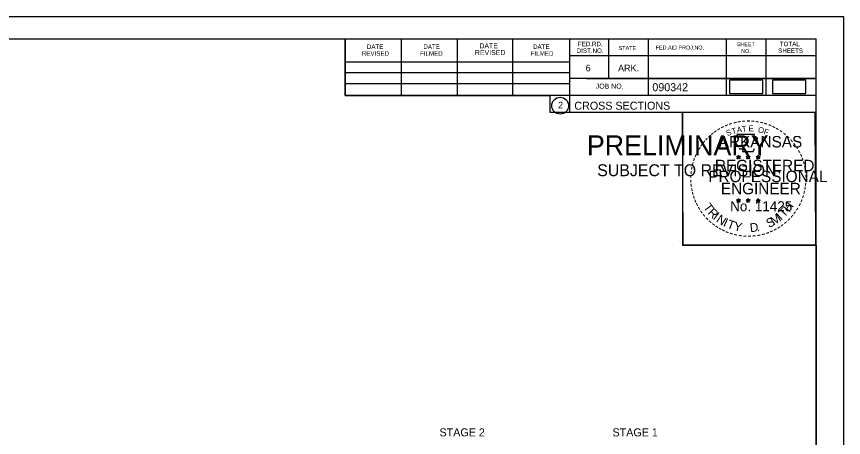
# Model space of a CAD drawing. Extents: x 1370515 to 1370849, y 383299 to 386073.
# Drawn here: x 1370704.3 to 1370848.7, y 385572.7 to 385646.1 of the extents above; entities that cross this region are included whole.
import ezdxf

# ---------------------------------------------------------------- set-up
doc = ezdxf.new("R2010")
doc.units = 0
for name, color, linetype in [('R_Axis Annot', 7, 'Continuous'), ('R_Border', 7, 'Continuous'), ('R_Border PE', 7, 'Continuous'), ('R_Border Prem', 7, 'Continuous'), ('R_Detour', 7, 'Continuous'), ('R_No Plot', 7, 'Continuous')]:
    doc.layers.add(name, color=color, linetype=linetype)

msp = doc.modelspace()

# ---------------------------------------------------------------- linework, layer by layer
at = {"layer": 'R_Border'}
for p, q in [((1370527.8, 385642.25), (1370843.98, 385642.25)), ((1370761.72, 385632.37), (1370761.72, 385642.25)), ((1370800.88, 385642.25), (1370800.88, 385629.45)), ((1370807.72, 385642.25), (1370807.72, 385635.31)), ((1370814.66, 385642.25), (1370814.66, 385632.37)), ((1370828.24, 385642.25), (1370828.24, 385632.37)), ((1370835.18, 385642.25), (1370835.18, 385632.37)), ((1370843.98, 385436.79), (1370843.98, 385642.25)), ((1370771.58, 385632.37), (1370771.58, 385642.05)), ((1370781.34, 385632.37), (1370781.34, 385642.05)), ((1370791.02, 385632.37), (1370791.02, 385642.05)), ((1370843.98, 385639.31), (1370800.88, 385639.31)), ((1370843.98, 385639.33), (1370843.98, 385639.33)), ((1370761.72, 385638.23), (1370800.88, 385638.23)), ((1370761.72, 385636.37), (1370800.88, 385636.37)), ((1370843.98, 385635.31), (1370800.88, 385635.31)), ((1370803.84, 385635.31), (1370843.98, 385635.31)), ((1370761.72, 385632.37), (1370761.72, 385634.43)), ((1370761.72, 385634.43), (1370800.88, 385634.43)), ((1370843.98, 385632.37), (1370761.72, 385632.37)), ((1370800.88, 385629.45), (1370843.98, 385629.45))]:
    msp.add_line(p, q, dxfattribs=at)
msp.add_circle((1370799.27, 385630.58), 1.47, dxfattribs=at)
at = {"layer": 'R_Border PE'}
for p, q in [((1370830.42, 385621.96), (1370830.37, 385621.71)), ((1370830.42, 385621.59), (1370830.42, 385621.96)), ((1370830.42, 385621.96), (1370830.46, 385621.71)), ((1370832.09, 385621.96), (1370832.04, 385621.71)), ((1370832.09, 385621.59), (1370832.09, 385621.96)), ((1370832.09, 385621.96), (1370832.13, 385621.71)), ((1370833.85, 385621.95), (1370833.81, 385621.69)), ((1370833.85, 385621.58), (1370833.85, 385621.95)), ((1370833.85, 385621.95), (1370833.9, 385621.7)), ((1370830.07, 385621.7), (1370830.42, 385621.59)), ((1370830.07, 385621.7), (1370830.32, 385621.66)), ((1370830.07, 385621.7), (1370830.3, 385621.58)), ((1370830.2, 385621.3), (1370830.42, 385621.59)), ((1370830.2, 385621.3), (1370830.33, 385621.54)), ((1370830.2, 385621.3), (1370830.41, 385621.51)), ((1370830.63, 385621.3), (1370830.41, 385621.51)), ((1370830.76, 385621.7), (1370830.42, 385621.59)), ((1370830.63, 385621.3), (1370830.42, 385621.59)), ((1370830.76, 385621.7), (1370830.48, 385621.65)), ((1370830.63, 385621.3), (1370830.49, 385621.59)), ((1370830.76, 385621.7), (1370830.56, 385621.6)), ((1370831.74, 385621.7), (1370832.09, 385621.59)), ((1370831.74, 385621.7), (1370831.99, 385621.66)), ((1370831.74, 385621.7), (1370831.97, 385621.58)), ((1370831.87, 385621.3), (1370832.09, 385621.59)), ((1370831.87, 385621.3), (1370832, 385621.54)), ((1370831.87, 385621.3), (1370832.08, 385621.51)), ((1370832.3, 385621.3), (1370832.08, 385621.51)), ((1370832.43, 385621.7), (1370832.09, 385621.59)), ((1370832.3, 385621.3), (1370832.09, 385621.59)), ((1370832.43, 385621.7), (1370832.15, 385621.65)), ((1370832.3, 385621.3), (1370832.16, 385621.59)), ((1370832.43, 385621.7), (1370832.23, 385621.6)), ((1370833.5, 385621.69), (1370833.85, 385621.58)), ((1370833.5, 385621.69), (1370833.75, 385621.65)), ((1370833.5, 385621.69), (1370833.74, 385621.57)), ((1370833.63, 385621.28), (1370833.85, 385621.58)), ((1370833.63, 385621.28), (1370833.76, 385621.53)), ((1370833.63, 385621.28), (1370833.85, 385621.5)), ((1370834.2, 385621.69), (1370833.85, 385621.58)), ((1370834.06, 385621.28), (1370833.85, 385621.58)), ((1370834.06, 385621.28), (1370833.85, 385621.5)), ((1370834.2, 385621.69), (1370833.91, 385621.64)), ((1370834.06, 385621.28), (1370833.93, 385621.57)), ((1370834.2, 385621.69), (1370833.99, 385621.59)), ((1370830.06, 385614.13), (1370830.41, 385614.02)), ((1370830.06, 385614.13), (1370830.32, 385614.09)), ((1370830.06, 385614.13), (1370830.3, 385614.01)), ((1370830.2, 385613.72), (1370830.41, 385614.02)), ((1370830.2, 385613.72), (1370830.32, 385613.97)), ((1370830.2, 385613.72), (1370830.41, 385613.94)), ((1370830.41, 385614.38), (1370830.37, 385614.13)), ((1370830.41, 385614.02), (1370830.41, 385614.38)), ((1370830.41, 385614.38), (1370830.46, 385614.13)), ((1370830.76, 385614.13), (1370830.41, 385614.02)), ((1370830.62, 385613.72), (1370830.41, 385614.02)), ((1370830.62, 385613.72), (1370830.41, 385613.94)), ((1370830.76, 385614.13), (1370830.47, 385614.08)), ((1370830.62, 385613.72), (1370830.49, 385614.01)), ((1370830.76, 385614.13), (1370830.55, 385614.03)), ((1370831.73, 385614.13), (1370832.08, 385614.02)), ((1370831.73, 385614.13), (1370831.98, 385614.09)), ((1370831.73, 385614.13), (1370831.97, 385614.01)), ((1370831.86, 385613.72), (1370832.08, 385614.02)), ((1370831.86, 385613.72), (1370831.99, 385613.97)), ((1370831.86, 385613.72), (1370832.08, 385613.94)), ((1370832.08, 385614.38), (1370832.04, 385614.13)), ((1370832.08, 385614.02), (1370832.08, 385614.38)), ((1370832.08, 385614.38), (1370832.13, 385614.13)), ((1370832.43, 385614.13), (1370832.08, 385614.02)), ((1370832.29, 385613.72), (1370832.08, 385614.02)), ((1370832.29, 385613.72), (1370832.08, 385613.94)), ((1370832.43, 385614.13), (1370832.14, 385614.08)), ((1370832.29, 385613.72), (1370832.16, 385614.01)), ((1370832.43, 385614.13), (1370832.22, 385614.03)), ((1370833.5, 385614.12), (1370833.85, 385614.01)), ((1370833.5, 385614.12), (1370833.75, 385614.08)), ((1370833.5, 385614.12), (1370833.74, 385614)), ((1370833.63, 385613.71), (1370833.85, 385614.01)), ((1370833.63, 385613.71), (1370833.76, 385613.96)), ((1370833.63, 385613.71), (1370833.85, 385613.93)), ((1370833.85, 385614.37), (1370833.81, 385614.12)), ((1370833.85, 385614.01), (1370833.85, 385614.37)), ((1370833.85, 385614.37), (1370833.9, 385614.12)), ((1370834.19, 385614.12), (1370833.85, 385614.01)), ((1370834.06, 385613.71), (1370833.85, 385614.01)), ((1370834.06, 385613.71), (1370833.85, 385613.93)), ((1370834.19, 385614.12), (1370833.91, 385614.07)), ((1370834.06, 385613.71), (1370833.92, 385614)), ((1370834.19, 385614.12), (1370833.99, 385614.02))]:
    msp.add_line(p, q, dxfattribs=at)
for points in [[(1370830.11, 385625.58), (1370830.38, 385624.75)], [(1370833.62, 385624.66), (1370833.76, 385624.94), (1370833.08, 385624.92), (1370833.22, 385625.58), (1370830.11, 385625.58)], [(1370830.42, 385621.96), (1370830.63, 385621.3), (1370830.07, 385621.7), (1370830.76, 385621.7), (1370830.2, 385621.3), (1370830.42, 385621.96)], [(1370830.6, 385623.16), (1370830.6, 385623.07), (1370831.16, 385623.05), (1370831.11, 385622.58), (1370832.98, 385622.58), (1370833.18, 385623.12)], [(1370832.09, 385621.96), (1370832.3, 385621.3), (1370831.74, 385621.7), (1370832.43, 385621.7), (1370831.87, 385621.3), (1370832.09, 385621.96)], [(1370833.85, 385621.95), (1370834.06, 385621.28), (1370833.5, 385621.69), (1370834.2, 385621.69), (1370833.63, 385621.28), (1370833.85, 385621.95)], [(1370830.41, 385614.38), (1370830.62, 385613.72), (1370830.06, 385614.13), (1370830.76, 385614.13), (1370830.2, 385613.72), (1370830.41, 385614.38)], [(1370832.08, 385614.38), (1370832.29, 385613.72), (1370831.73, 385614.13), (1370832.43, 385614.13), (1370831.86, 385613.72), (1370832.08, 385614.38)], [(1370833.85, 385614.37), (1370834.06, 385613.71), (1370833.5, 385614.12), (1370834.19, 385614.12), (1370833.63, 385613.71), (1370833.85, 385614.37)]]:
    msp.add_lwpolyline(points, dxfattribs=at)
for centre, radius in [((1370830.41, 385621.59), 0.172), ((1370830.41, 385621.59), 0.145), ((1370830.41, 385621.59), 0.116), ((1370830.41, 385621.59), 0.0991), ((1370830.41, 385621.59), 0.0747), ((1370830.41, 385621.59), 0.0495), ((1370830.41, 385621.59), 0.0296), ((1370832.08, 385621.59), 0.172), ((1370832.08, 385621.59), 0.145), ((1370832.08, 385621.59), 0.116), ((1370832.08, 385621.59), 0.0991), ((1370832.08, 385621.59), 0.0747), ((1370832.08, 385621.59), 0.0495), ((1370832.08, 385621.59), 0.0296), ((1370833.85, 385621.58), 0.172), ((1370833.85, 385621.58), 0.145), ((1370833.85, 385621.58), 0.116), ((1370833.85, 385621.58), 0.0991), ((1370833.85, 385621.58), 0.0747), ((1370833.85, 385621.58), 0.0495), ((1370833.85, 385621.58), 0.0296), ((1370830.41, 385614.02), 0.172), ((1370830.41, 385614.02), 0.145), ((1370830.41, 385614.02), 0.116), ((1370830.41, 385614.02), 0.0991), ((1370830.41, 385614.02), 0.0747), ((1370830.41, 385614.02), 0.0495), ((1370830.41, 385614.02), 0.0296), ((1370832.08, 385614.02), 0.172), ((1370832.08, 385614.02), 0.145), ((1370832.08, 385614.02), 0.116), ((1370832.08, 385614.02), 0.0991), ((1370832.08, 385614.02), 0.0747), ((1370832.08, 385614.02), 0.0495), ((1370832.08, 385614.02), 0.0296), ((1370833.85, 385614.01), 0.172), ((1370833.85, 385614.01), 0.145), ((1370833.85, 385614.01), 0.116), ((1370833.85, 385614.01), 0.0991), ((1370833.85, 385614.01), 0.0747), ((1370833.85, 385614.01), 0.0495), ((1370833.85, 385614.01), 0.0296)]:
    msp.add_circle(centre, radius, dxfattribs=at)
at = {"layer": 'R_Detour'}
for points in [[(1370828.81, 385632.7), (1370834.64, 385632.7), (1370834.64, 385635.01), (1370828.81, 385635.01)], [(1370836.36, 385632.7), (1370842.19, 385632.7), (1370842.19, 385635.01), (1370836.36, 385635.01)]]:
    msp.add_lwpolyline(points, close=True, dxfattribs=at)
at = {"layer": 'R_No Plot'}
for p, q in [((1370515.4, 385646.14), (1370848.73, 385646.14)), ((1370820.02, 385606.99), (1370820.02, 385606.99))]:
    msp.add_line(p, q, dxfattribs=at)
for points in [[(1370515.39, 385646.14), (1370848.73, 385646.14), (1370848.73, 385432.81), (1370515.39, 385432.81)], [(1370761.72, 385642.25), (1370761.72, 385632.37), (1370797.45, 385632.37), (1370797.45, 385629.45), (1370820.65, 385629.45), (1370820.65, 385606.23), (1370843.98, 385606.23), (1370843.98, 385436.79), (1370527.8, 385436.79), (1370527.8, 385642.25)], [(1370820.65, 385629.48), (1370843.75, 385629.48), (1370843.87, 385606.23), (1370820.77, 385606.23)]]:
    msp.add_lwpolyline(points, close=True, dxfattribs=at)

# ---------------------------------------------------------------- texts
at = {"layer": 'R_Axis Annot'}
for s, p in [('STAGE 2', (1370778.2, 385572.86)), ('STAGE 1', (1370808.41, 385572.86))]:
    msp.add_text(s, height=1.4, dxfattribs=at).set_placement(p)
at = {"layer": 'R_Border'}
for s, height, p in [('DATE', 0.782, (1370765.52, 385640.49)), ('DATE', 0.782, (1370775.38, 385640.49)), ('DATE', 0.879, (1370785.16, 385640.59)), ('DATE', 0.782, (1370794.54, 385640.49)), ('FED.RD.', 0.782, (1370802.36, 385640.97)), ('STATE', 0.684, (1370809.48, 385640.29)), ('FED.AID PROJ.NO.', 0.684, (1370815.94, 385640.39)), ('SHEET', 0.684, (1370830.1, 385640.97)), ('TOTAL', 0.782, (1370837.62, 385640.97)), ('REVISED', 0.782, (1370764.64, 385639.31)), ('FILMED', 0.782, (1370774.8, 385639.31)), ('REVISED', 0.879, (1370784.38, 385639.41)), ('FILMED', 0.782, (1370794.14, 385639.31)), ('DIST.NO.', 0.782, (1370802.16, 385639.79)), ('NO.', 0.684, (1370830.88, 385639.79)), ('SHEETS', 0.782, (1370837.34, 385639.79)), ('6', 1.17, (1370803.72, 385636.57)), ('ARK.', 1.172, (1370809.38, 385636.57)), ('JOB NO.', 0.879, (1370805.48, 385633.55)), ('090342', 1.4, (1370815.36, 385633.11)), ('2', 1.17, (1370798.89, 385630.1)), ('CROSS SECTIONS', 1.4, (1370801.74, 385629.88))]:
    msp.add_text(s, height=height, rotation=360, dxfattribs=at).set_placement(p)
at = {"layer": 'R_Border PE'}
for s, height, rotation, p in [('-', 1.6, 13.6301, (1370829.61, 385626.95)), ('-', 1.6, 10.2193, (1370830.28, 385627.11)), ('-', 1.6, 5.8968, (1370831.01, 385627.22)), ('-', 1.6, 0.1862, (1370831.78, 385627.29)), ('-', 1.6, 357.743, (1370832.51, 385627.28)), ('-', 1.6, 352.1617, (1370833.25, 385627.22)), ('-', 1.6, 347.2049, (1370833.97, 385627.11)), ('-', 1.6, 36.2317, (1370826.41, 385625.36)), ('-', 1.6, 34.0636, (1370826.99, 385625.75)), ('-', 1.6, 28.7918, (1370827.59, 385626.12)), ('-', 1.6, 24.3072, (1370828.22, 385626.44)), ('S', 1, 21.594, (1370828.46, 385625.26)), ('-', 1.6, 19.1761, (1370828.86, 385626.71)), ('T', 1, 16.4036, (1370829.38, 385625.59)), ('A', 1, 11.2132, (1370830.2, 385625.84)), ('T', 1, 6.0228, (1370831.05, 385626.01)), ('E', 1, 0.8323, (1370832.16, 385626.12)), ('O', 1, 350.4515, (1370833.76, 385625.91)), ('F', 1, 340.0707, (1370834.71, 385625.68)), ('-', 1.6, 342.3362, (1370834.61, 385626.96)), ('-', 1.6, 337.8551, (1370835.34, 385626.73)), ('-', 1.6, 334.1211, (1370835.97, 385626.46)), ('-', 1.6, 329.6409, (1370836.55, 385626.18)), ('-', 1.6, 325.8627, (1370837.19, 385625.82)), ('-', 1.6, 48.423, (1370825.06, 385624.08)), ('-', 1.6, 42.9622, (1370825.5, 385624.56)), ('-', 1.6, 38.9507, (1370825.94, 385624.98)), ('ARKANSAS', 2, 360, (1370826.96, 385623.29)), ('-', 1.6, 320.5297, (1370837.8, 385625.39)), ('-', 1.6, 315.5786, (1370838.4, 385624.9)), ('-', 1.6, 58.0706, (1370823.92, 385622.5)), ('-', 1.6, 54.2325, (1370824.24, 385623.03)), ('-', 1.6, 50.6142, (1370824.65, 385623.6)), ('-', 1.6, 309.8797, (1370838.97, 385624.35)), ('-', 1.6, 306.6522, (1370839.5, 385623.75)), ('-', 1.4, 303.6753, (1370839.98, 385623.18)), ('-', 1.6, 67.7743, (1370823.34, 385621.28)), ('-', 1.6, 62.8713, (1370823.6, 385621.89)), ('-', 1.6, 299.6684, (1370840.3, 385622.58)), ('-', 1.6, 294.6628, (1370840.63, 385621.96)), ('-', 1.6, 75.461, (1370822.93, 385619.94)), ('-', 1.6, 72.3945, (1370823.12, 385620.65)), ('REGISTERED', 2, 360, (1370826.28, 385619.14)), ('DWB', 0.01, 360, (1370830.4, 385621.59)), ('DWB', 0.01, 360, (1370832.07, 385621.59)), ('DWB', 0.01, 360, (1370833.84, 385621.58)), ('-', 1.6, 290.5728, (1370840.88, 385621.39)), ('-', 1.6, 285.1233, (1370841.12, 385620.81)), ('-', 1.6, 85.1863, (1370822.72, 385618.53)), ('-', 1.6, 81.2013, (1370822.8, 385619.22)), ('PROFESSIONAL', 2, 360, (1370825.13, 385617.24)), ('-', 1.6, 280.5493, (1370841.32, 385620.07)), ('-', 1.6, 276.5962, (1370841.48, 385619.3)), ('-', 1.6, 94.1959, (1370822.73, 385617.11)), ('-', 1.6, 89.0622, (1370822.69, 385617.83)), ('-', 1.6, 274.3301, (1370841.54, 385618.58)), ('-', 1.6, 269.9407, (1370841.57, 385617.94)), ('-', 1.6, 98.9479, (1370822.8, 385616.44)), ('-', 1.6, 101.7149, (1370822.94, 385615.71)), ('ENGINEER', 2, 360, (1370827.32, 385615.12)), ('-', 1.6, 260.9953, (1370841.48, 385616.62)), ('-', 1.6, 263.5172, (1370841.55, 385617.28)), ('-', 1.6, 105.4578, (1370823.1, 385615.11)), ('-', 1.6, 109.0874, (1370823.31, 385614.48)), ('-', 1.6, 252.8681, (1370841.19, 385615.23)), ('-', 1.6, 255.7626, (1370841.37, 385615.95)), ('-', 1.6, 114.0643, (1370823.57, 385613.88)), ('-', 1.6, 115.7288, (1370823.87, 385613.27)), ('T', 1.54, 306.0406, (1370824.17, 385612.86)), ('No. 11425', 1.757, 360, (1370828.95, 385612.16)), ('DWB', 0.01, 360, (1370830.4, 385614.01)), ('DWB', 0.01, 360, (1370832.07, 385614.02)), ('DWB', 0.01, 360, (1370833.83, 385614.01)), ('H', 1.54, 54.6088, (1370839.29, 385611.89)), ('-', 1.6, 244.6197, (1370840.71, 385613.92)), ('-', 1.6, 247.8887, (1370840.97, 385614.55)), ('-', 1.6, 120.4471, (1370824.23, 385612.68)), ('-', 1.6, 125.8934, (1370824.63, 385612.12)), ('R', 1.54, 314.005, (1370824.93, 385611.81)), ('I', 1.54, 321.9694, (1370825.83, 385610.88)), ('I', 1.54, 42.1136, (1370837.84, 385610.47)), ('T', 1.54, 46.6444, (1370838.4, 385610.95)), ('-', 1.6, 233.8452, (1370839.91, 385612.52)), ('-', 1.6, 239.0712, (1370840.31, 385613.17)), ('-', 1.6, 130.7181, (1370825.09, 385611.57)), ('-', 1.6, 134.2238, (1370825.61, 385611.02)), ('-', 1.6, 138.9338, (1370826.14, 385610.56)), ('N', 1.54, 326.5002, (1370826.4, 385610.41)), ('I', 1.54, 335.3603, (1370827.61, 385609.62)), ('T', 1.54, 339.8912, (1370828.27, 385609.29)), ('S', 1.54, 26.9312, (1370835.72, 385609.22)), ('M', 1.54, 32.6563, (1370836.56, 385609.63)), ('-', 1.6, 221.0851, (1370838.48, 385610.88)), ('-', 1.6, 225.7653, (1370839, 385611.39)), ('-', 1.6, 231.2538, (1370839.48, 385611.95)), ('-', 1.6, 144.6463, (1370826.69, 385610.15)), ('-', 1.6, 148.0898, (1370827.25, 385609.78)), ('-', 1.6, 151.5704, (1370827.83, 385609.46)), ('-', 1.6, 154.6002, (1370828.35, 385609.21)), ('Y', 1.54, 347.8556, (1370829.49, 385608.85)), ('D', 1.54, 6.3969, (1370832.47, 385608.49)), ('.', 1.54, 13.7642, (1370833.66, 385608.62)), ('-', 1.6, 207.3568, (1370836.84, 385609.67)), ('-', 1.6, 212.2491, (1370837.4, 385610.02)), ('-', 1.6, 215.7363, (1370837.93, 385610.41)), ('-', 1.6, 158.5612, (1370828.98, 385608.95)), ('-', 1.6, 162.7983, (1370829.67, 385608.74)), ('-', 1.6, 167.5555, (1370830.38, 385608.58)), ('-', 1.6, 173.1155, (1370831.15, 385608.47)), ('-', 1.6, 176.5183, (1370831.9, 385608.41)), ('-', 1.6, 181.5918, (1370832.64, 385608.43)), ('-', 1.6, 185.8167, (1370833.45, 385608.51)), ('-', 1.6, 191.2858, (1370834.19, 385608.64)), ('-', 1.6, 195.4743, (1370834.92, 385608.84)), ('-', 1.6, 200.7184, (1370835.6, 385609.08)), ('-', 1.6, 204.2516, (1370836.21, 385609.36))]:
    msp.add_text(s, height=height, rotation=rotation, dxfattribs=at).set_placement(p)
at = {"layer": 'R_Border Prem'}
for s, height, p in [('PRELIMINARY', 3.5, (1370803.93, 385621.91)), ('DWB', 0.01, (1370804.68, 385623.76)), ('SUBJECT TO REVISION', 2.0751, (1370805.74, 385618.28))]:
    msp.add_text(s, height=height, rotation=360, dxfattribs=at).set_placement(p)

doc.saveas('drawing.dxf')
